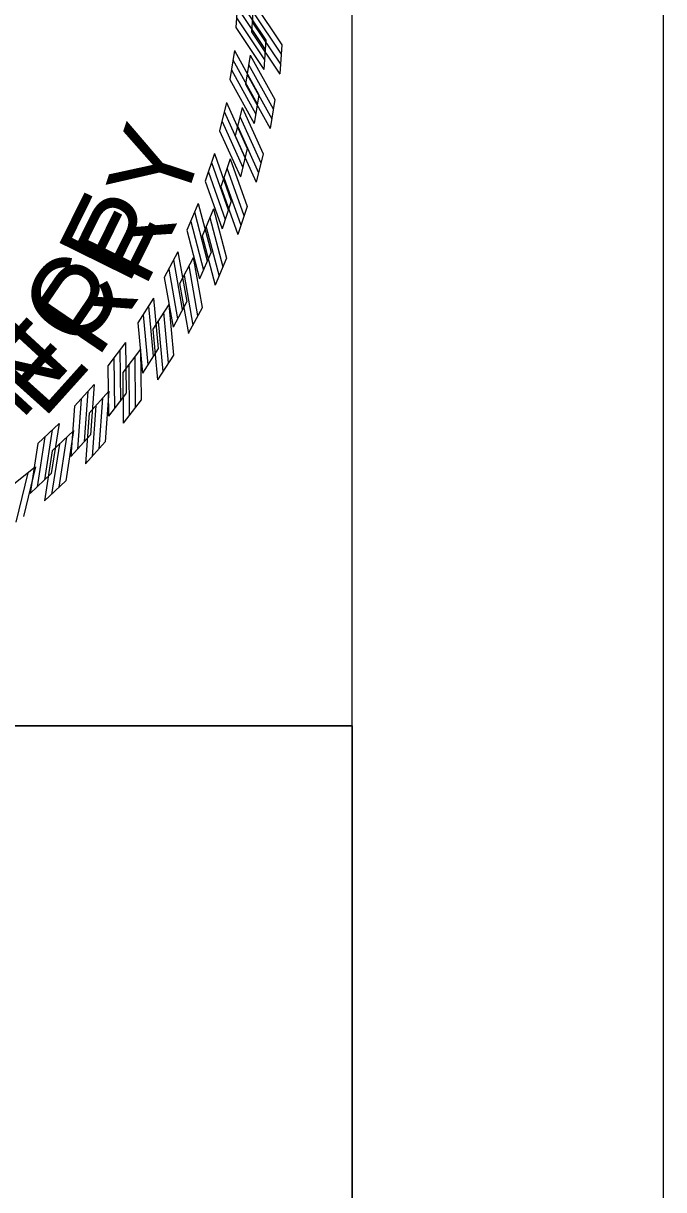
# Model space of a CAD drawing. Extents: x 0 to 1228740, y 0 to 152440.
# Drawn here: x 32.814 to 34, y 16.545 to 18.707 of the extents above; entities that cross this region are included whole.
import ezdxf

# ---------------------------------------------------------------- set-up
doc = ezdxf.new("R2010")
doc.units = 0
for name, color, linetype in [('R_Border', 7, 'Continuous'), ('R_No Plot', 7, 'Continuous'), ('STAMP_Byron', 7, 'Continuous'), ('STAMP_PP', 7, 'Continuous')]:
    doc.layers.add(name, color=color, linetype=linetype)

msp = doc.modelspace()

# ---------------------------------------------------------------- linework, layer by layer
at = {"layer": 'R_Border'}
msp.add_line((33.4231, 0.5768), (33.4231, 21.4232), dxfattribs=at)
msp.add_lwpolyline([(33.9999, 22), (0, 22), (0, 0), (33.9999, 0)], close=True, dxfattribs=at)
at = {"layer": 'R_No Plot'}
for points in [[(33.4231, 17.4052), (33.4231, 10.8708), (1.516, 10.8708), (1.516, 21.4232), (25.1971, 21.4232), (25.1971, 20.4352), (28.7491, 20.4352), (28.7491, 20.0782), (29.1131, 20.0782), (29.1131, 20.1432), (30.6665, 20.1432)], [(30.6665, 20.1432), (30.6665, 17.4052), (33.4231, 17.4052)], [(33.4231, 17.4052), (30.6665, 17.4052), (30.6665, 20.1432)], [(33.4231, 10.8708), (33.4231, 17.4052)]]:
    msp.add_lwpolyline(points, dxfattribs=at)
at = {"layer": 'STAMP_Byron'}
for p, q in [((33.2111, 18.7538), (33.2071, 18.6997)), ((33.2111, 18.7538), (33.2071, 18.6997)), ((33.263, 18.676), (33.2591, 18.6221)), ((33.263, 18.676), (33.2591, 18.6221)), ((33.2046, 18.6568), (33.1962, 18.6033)), ((33.2046, 18.6568), (33.1962, 18.6033)), ((33.2499, 18.575), (33.2415, 18.5216)), ((33.2499, 18.575), (33.2415, 18.5216)), ((33.1901, 18.5606), (33.1773, 18.508)), ((33.1901, 18.5606), (33.1773, 18.508)), ((33.1677, 18.466), (33.1506, 18.4147)), ((33.1677, 18.466), (33.1506, 18.4147)), ((33.2285, 18.4754), (33.2157, 18.4229)), ((33.2285, 18.4754), (33.2157, 18.4229)), ((33.1989, 18.3779), (33.1819, 18.3266)), ((33.1989, 18.3779), (33.1819, 18.3266)), ((33.1376, 18.3736), (33.1163, 18.3238)), ((33.1376, 18.3736), (33.1163, 18.3238)), ((33.0999, 18.284), (33.0746, 18.2361)), ((33.0999, 18.284), (33.0746, 18.2361)), ((33.1614, 18.2832), (33.1402, 18.2335)), ((33.1614, 18.2832), (33.1402, 18.2335)), ((33.055, 18.1978), (33.0258, 18.1522)), ((33.055, 18.1978), (33.0258, 18.1522)), ((33.1162, 18.1919), (33.0909, 18.1441)), ((33.1162, 18.1919), (33.0909, 18.1441)), ((33.0031, 18.1156), (32.9702, 18.0725)), ((33.0031, 18.1156), (32.9702, 18.0725)), ((33.0636, 18.1047), (33.0345, 18.0592)), ((33.0636, 18.1047), (33.0345, 18.0592)), ((32.9446, 18.0379), (32.9083, 17.9978)), ((32.9446, 18.0379), (32.9083, 17.9978)), ((33.004, 18.0221), (32.9712, 17.9791)), ((33.004, 18.0221), (32.9712, 17.9791)), ((32.8799, 17.9654), (32.8403, 17.9284)), ((32.8799, 17.9654), (32.8403, 17.9284)), ((32.9378, 17.9447), (32.9016, 17.9046)), ((32.9378, 17.9447), (32.9016, 17.9046)), ((32.8654, 17.873), (32.826, 17.836)), ((32.8654, 17.873), (32.826, 17.836))]:
    msp.add_line(p, q, dxfattribs=at)
for points in [[(33.2111, 18.7538), (33.263, 18.6761)], [(33.2111, 18.7538), (33.263, 18.6761)], [(33.2096, 18.7365), (33.2616, 18.6587)], [(33.2096, 18.7365), (33.2616, 18.6587)], [(33.2087, 18.7177), (33.2606, 18.64)], [(33.2087, 18.7177), (33.2606, 18.64)], [(33.2072, 18.6998), (33.2591, 18.6221)], [(33.2072, 18.6998), (33.2591, 18.6221)], [(33.2017, 18.6397), (33.247, 18.5579)], [(33.2017, 18.6397), (33.247, 18.5579)], [(33.2045, 18.6568), (33.2499, 18.5751)], [(33.2045, 18.6568), (33.2499, 18.5751)], [(33.1992, 18.6211), (33.2445, 18.5393)], [(33.1992, 18.6211), (33.2445, 18.5393)], [(33.1962, 18.6033), (33.2415, 18.5215)], [(33.1962, 18.6033), (33.2415, 18.5215)], [(33.19, 18.5607), (33.2285, 18.4755)], [(33.19, 18.5607), (33.2285, 18.4755)], [(33.1858, 18.5439), (33.2242, 18.4586)], [(33.1858, 18.5439), (33.2242, 18.4586)], [(33.1773, 18.5081), (33.2158, 18.4228)], [(33.1773, 18.5081), (33.2158, 18.4228)], [(33.1817, 18.5255), (33.2202, 18.4403)], [(33.1817, 18.5255), (33.2202, 18.4403)], [(33.1677, 18.4661), (33.1989, 18.378)], [(33.1677, 18.4661), (33.1989, 18.378)], [(33.162, 18.4497), (33.1933, 18.3615)], [(33.162, 18.4497), (33.1933, 18.3615)], [(33.1565, 18.4317), (33.1877, 18.3436)], [(33.1565, 18.4317), (33.1877, 18.3436)], [(33.1506, 18.4147), (33.1819, 18.3266)], [(33.1506, 18.4147), (33.1819, 18.3266)], [(33.1306, 18.3578), (33.1544, 18.2674)], [(33.1306, 18.3578), (33.1544, 18.2674)], [(33.1375, 18.3737), (33.1614, 18.2833)], [(33.1375, 18.3737), (33.1614, 18.2833)], [(33.1236, 18.3403), (33.1474, 18.2499)], [(33.1236, 18.3403), (33.1474, 18.2499)], [(33.1163, 18.3239), (33.1402, 18.2335)], [(33.1163, 18.3239), (33.1402, 18.2335)], [(33.0999, 18.2841), (33.1162, 18.192)], [(33.0999, 18.2841), (33.1162, 18.192)], [(33.0832, 18.252), (33.0995, 18.1599)], [(33.0832, 18.252), (33.0995, 18.1599)], [(33.0916, 18.2688), (33.1079, 18.1767)], [(33.0916, 18.2688), (33.1079, 18.1767)], [(33.0746, 18.2362), (33.091, 18.1441)], [(33.0746, 18.2362), (33.091, 18.1441)], [(33.0455, 18.1833), (33.0541, 18.0902)], [(33.0455, 18.1833), (33.0541, 18.0902)], [(33.055, 18.1979), (33.0636, 18.1048)], [(33.055, 18.1979), (33.0636, 18.1048)], [(33.0357, 18.1673), (33.0444, 18.0742)], [(33.0357, 18.1673), (33.0444, 18.0742)], [(33.0258, 18.1522), (33.0345, 18.0591)], [(33.0258, 18.1522), (33.0345, 18.0591)], [(32.9924, 18.1019), (32.9933, 18.0084)], [(32.9924, 18.1019), (32.9933, 18.0084)], [(33.0031, 18.1157), (33.004, 18.0222)], [(33.0031, 18.1157), (33.004, 18.0222)], [(32.9813, 18.0868), (32.9823, 17.9933)], [(32.9813, 18.0868), (32.9823, 17.9933)], [(32.9703, 18.0726), (32.9712, 17.9791)], [(32.9703, 18.0726), (32.9712, 17.9791)], [(32.9446, 18.038), (32.9378, 17.9448)], [(32.9446, 18.038), (32.9378, 17.9448)], [(32.9205, 18.011), (32.9137, 17.9178)], [(32.9205, 18.011), (32.9137, 17.9178)], [(32.9328, 18.0252), (32.926, 17.932)], [(32.9328, 18.0252), (32.926, 17.932)], [(32.9083, 17.9978), (32.9016, 17.9045)], [(32.9083, 17.9978), (32.9016, 17.9045)], [(32.8671, 17.9537), (32.8526, 17.8613)], [(32.8671, 17.9537), (32.8526, 17.8613)], [(32.8799, 17.9655), (32.8654, 17.8731)], [(32.8799, 17.9655), (32.8654, 17.8731)], [(32.8404, 17.9284), (32.826, 17.836)], [(32.8404, 17.9284), (32.826, 17.836)], [(32.8537, 17.9406), (32.8392, 17.8482)], [(32.8537, 17.9406), (32.8392, 17.8482)]]:
    msp.add_lwpolyline(points, dxfattribs=at)
at = {"layer": 'STAMP_PP'}
for p, q in [((33.2402, 18.746), (33.2362, 18.6916)), ((33.2925, 18.6677), (33.2885, 18.6135)), ((33.2337, 18.6484), (33.2252, 18.5945)), ((33.2191, 18.5516), (33.2062, 18.4986)), ((33.2793, 18.566), (33.2708, 18.5123)), ((33.2577, 18.4657), (33.2449, 18.4129)), ((33.1965, 18.4563), (33.1793, 18.4046)), ((33.1662, 18.3633), (33.1447, 18.3131)), ((33.228, 18.3676), (33.2108, 18.316)), ((33.1283, 18.273), (33.1027, 18.2248)), ((33.1902, 18.2722), (33.1688, 18.2222)), ((33.083, 18.1863), (33.0536, 18.1403)), ((33.1447, 18.1803), (33.1192, 18.1323)), ((33.0308, 18.1035), (32.9977, 18.0601)), ((33.0917, 18.0925), (33.0624, 18.0467)), ((32.9719, 18.0253), (32.9353, 17.9849)), ((33.0317, 18.0093), (32.9987, 17.9661)), ((32.9067, 17.9523), (32.8669, 17.915)), ((32.965, 17.9314), (32.9286, 17.8911)), ((32.8357, 17.8849), (32.793, 17.851)), ((32.8922, 17.8593), (32.8525, 17.8221))]:
    msp.add_line(p, q, dxfattribs=at)
for points in [[(33.2402, 18.7461), (33.2925, 18.6678)], [(33.2387, 18.7286), (33.291, 18.6503)], [(33.2378, 18.7098), (33.29, 18.6315)], [(33.2363, 18.6917), (33.2885, 18.6134)], [(33.2336, 18.6484), (33.2793, 18.5661)], [(33.2307, 18.6312), (33.2764, 18.5488)], [(33.2252, 18.5945), (33.2709, 18.5122)], [(33.2282, 18.6124), (33.2739, 18.5301)], [(33.219, 18.5517), (33.2577, 18.4658)], [(33.2147, 18.5347), (33.2534, 18.4489)], [(33.2107, 18.5162), (33.2493, 18.4304)], [(33.2062, 18.4986), (33.2449, 18.4128)], [(33.1965, 18.4564), (33.228, 18.3677)], [(33.1852, 18.4218), (33.2167, 18.3331)], [(33.1908, 18.4398), (33.2223, 18.3511)], [(33.1793, 18.4046), (33.2108, 18.3159)], [(33.1662, 18.3634), (33.1902, 18.2723)], [(33.1591, 18.3473), (33.1832, 18.2563)], [(33.1448, 18.3132), (33.1688, 18.2222)], [(33.1521, 18.3298), (33.1761, 18.2388)], [(33.1282, 18.2731), (33.1447, 18.1804)], [(33.1199, 18.2577), (33.1364, 18.165)], [(33.1114, 18.2408), (33.1279, 18.1481)], [(33.1028, 18.2249), (33.1193, 18.1322)], [(33.083, 18.1863), (33.0917, 18.0926)], [(33.0734, 18.1717), (33.0822, 18.0779)], [(33.0537, 18.1404), (33.0624, 18.0466)], [(33.0636, 18.1555), (33.0723, 18.0618)], [(33.0308, 18.1036), (33.0317, 18.0094)], [(33.02, 18.0898), (33.021, 17.9956)], [(32.9977, 18.0602), (32.9987, 17.966)], [(33.0089, 18.0745), (33.0098, 17.9803)], [(32.96, 18.0125), (32.9532, 17.9186)], [(32.9719, 18.0254), (32.9651, 17.9315)], [(32.9477, 17.9982), (32.9408, 17.9043)], [(32.9354, 17.9849), (32.9286, 17.891)], [(32.9067, 17.9524), (32.8922, 17.8594)], [(32.8803, 17.9273), (32.8658, 17.8343)], [(32.8938, 17.9405), (32.8793, 17.8475)], [(32.867, 17.915), (32.8525, 17.822)], [(32.8358, 17.885), (32.8136, 17.7935)], [(32.8219, 17.8742), (32.7998, 17.7827)]]:
    msp.add_lwpolyline(points, dxfattribs=at)

# ---------------------------------------------------------------- texts
at = {"layer": 'STAMP_Byron'}
for s, rotation, p in [('E', 63.7362, (33.0074, 18.2196)), ('E', 63.7362, (33.0074, 18.2196)), ('C', 56.0754, (32.9235, 18.0957)), ('C', 56.0754, (32.9235, 18.0957)), ('N', 47.3202, (32.8085, 17.9694)), ('N', 47.3202, (32.8085, 17.9694))]:
    msp.add_text(s, height=0.1493, rotation=rotation, dxfattribs=at).set_placement(p)
at = {"layer": 'STAMP_PP'}
for s, rotation, p in [('Y', 71.7733, (33.1072, 18.3567)), ('R', 63.7477, (33.0384, 18.2148)), ('R', 55.7221, (32.9504, 18.084)), ('E', 48.0613, (32.8502, 17.9717))]:
    msp.add_text(s, height=0.1503, rotation=rotation, dxfattribs=at).set_placement(p)

doc.saveas('drawing.dxf')
